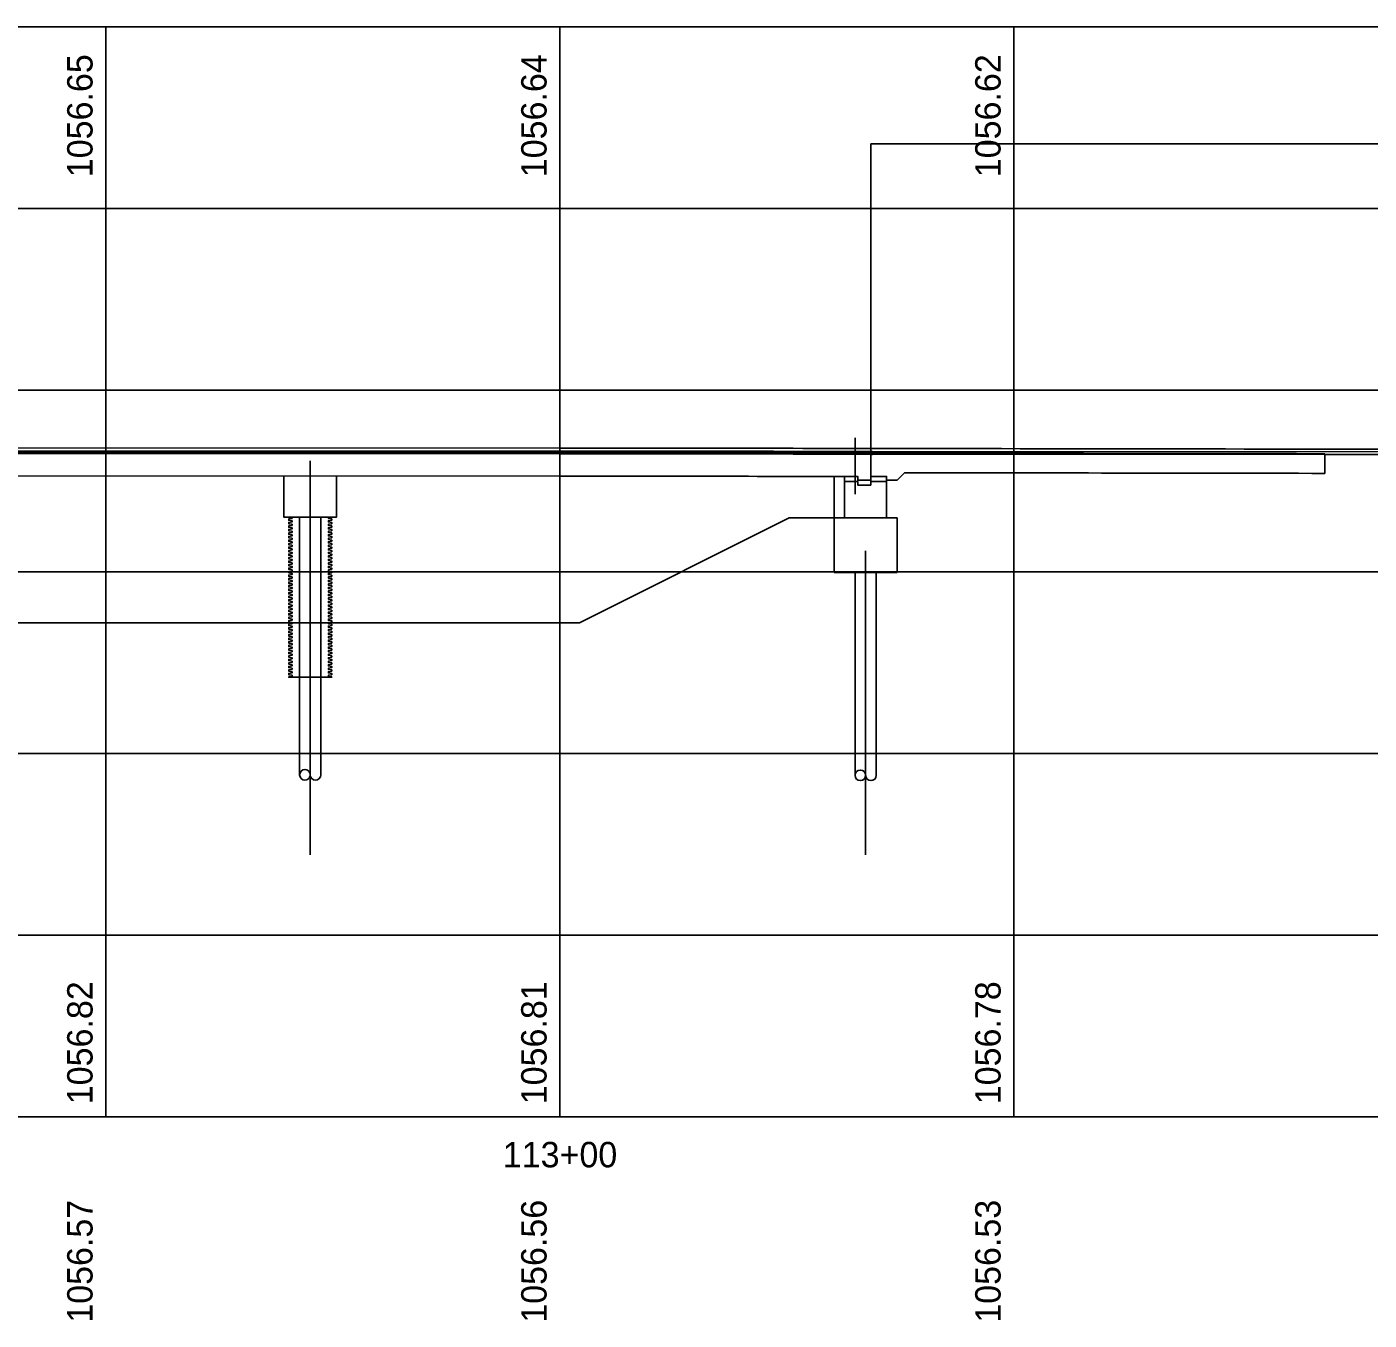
# Model space of a CAD drawing. Extents: x -2063 to 2068, y 79 to 1202.
# Drawn here: x -1598.7 to -1524.8, y 250.8 to 322 of the extents above; entities that cross this region are included whole.
import ezdxf

# ---------------------------------------------------------------- set-up
doc = ezdxf.new("R2010")
doc.units = 0
for name, color, linetype in [('BR_P_Gen_Approach_Slab', 7, 'Continuous'), ('BR_P_Gen_Joint_Filler', 7, 'Continuous'), ('BR_P_Slab_Object', 7, 'Continuous'), ('BR_X_Brg_Centerline', 7, 'Continuous'), ('BR_X_Gen_Approach_Slab', 7, 'Continuous'), ('BR_X_Slab_Object', 7, 'Continuous'), ('BR_X_Sub_Deep_Centerline', 7, 'Continuous'), ('BR_X_Sub_Deep_Object', 7, 'Continuous'), ('BR_X_Sub_Object', 7, 'Continuous'), ('PF_X_Ground_Line', 7, 'Continuous'), ('SC_Scratch1', 7, 'Continuous'), ('SC_Scratch2', 7, 'Continuous'), ('SC_Scratch3', 7, 'Continuous'), ('XS_P_Pavt_Surface', 7, 'Continuous')]:
    doc.layers.add(name, color=color, linetype=linetype)

msp = doc.modelspace()

# ---------------------------------------------------------------- linework, layer by layer
at = {"layer": 'BR_P_Gen_Approach_Slab'}
msp.add_line((-1552.207, 298.444), (-1527.207, 298.432), dxfattribs=at)
at = {"layer": 'BR_P_Gen_Joint_Filler'}
msp.add_lwpolyline([(-1552.207, 298.59), (-1552.123, 298.59), (-1552.123, 298.423), (-1552.207, 298.423)], close=True, dxfattribs=at)
at = {"layer": 'BR_P_Slab_Object'}
msp.add_line((-1552.207, 298.59), (-1552.207, 298.444), dxfattribs=at)
for points in [[(-1651.447, 298.617), (-1619.327, 298.63), (-1569.327, 298.61)], [(-1569.327, 298.464), (-1619.327, 298.484), (-1651.447, 298.471)]]:
    msp.add_lwpolyline(points, dxfattribs=at)
for centre in [(-1573.973, -11316.689), (-1573.973, -11316.835)]:
    msp.add_arc(centre, 11615.3, 89.8926323, 89.9770817, dxfattribs=at)
at = {"layer": 'BR_X_Brg_Centerline'}
for p, q in [((-1553.073, 299.349), (-1553.073, 296.245)), ((-1583.077, 298.081), (-1583.077, 276.394))]:
    msp.add_line(p, q, dxfattribs=at)
at = {"layer": 'BR_X_Gen_Approach_Slab'}
msp.add_line((-1527.207, 298.47), (-1527.207, 297.387), dxfattribs=at)
msp.add_lwpolyline([(-1550.352, 297.421), (-1550.763, 297.009), (-1551.341, 297.009)], dxfattribs=at)
for centre, end in [((-1631.827, -62201.629), 89.9270098), ((-1631.827, -62202.712), 89.92530917)]:
    msp.add_arc(centre, 62500.186, 89.90409154, end, dxfattribs=at)
at = {"layer": 'BR_X_Slab_Object'}
msp.add_line((-1552.207, 297.218), (-1552.207, 298.507), dxfattribs=at)
for points in [[(-1569.327, 298.526), (-1619.327, 298.546), (-1651.447, 298.533)], [(-1649.426, 297.243), (-1619.327, 297.255), (-1569.327, 297.235)]]:
    msp.add_lwpolyline(points, dxfattribs=at)
for centre, start in [((-1631.827, -62201.629), 89.9270098), ((-1631.827, -62202.92), 89.92886227)]:
    msp.add_arc(centre, 62500.186, start, 89.94270423, dxfattribs=at)
at = {"layer": 'BR_X_Sub_Deep_Centerline'}
msp.add_line((-1552.495, 293.128), (-1552.495, 276.394), dxfattribs=at)
at = {"layer": 'BR_X_Sub_Deep_Object'}
for p, q in [((-1583.66, 294.969), (-1583.66, 280.794)), ((-1582.493, 294.969), (-1582.493, 280.794)), ((-1553.075, 280.764), (-1553.075, 291.936)), ((-1551.909, 280.764), (-1551.909, 291.936))]:
    msp.add_line(p, q, dxfattribs=at)
msp.add_lwpolyline([(-1584.077, 294.969), (-1584.077, 294.907), (-1584.26, 294.876), (-1584.26, 294.808), (-1584.077, 294.776), (-1584.077, 294.714), (-1584.26, 294.683), (-1584.26, 294.614), (-1584.077, 294.583), (-1584.077, 294.523), (-1584.26, 294.492), (-1584.26, 294.423), (-1584.077, 294.392), (-1584.077, 294.33), (-1584.26, 294.298), (-1584.26, 294.23), (-1584.077, 294.199), (-1584.077, 294.136), (-1584.26, 294.105), (-1584.26, 294.037), (-1584.077, 294.006), (-1584.077, 293.943), (-1584.26, 293.912), (-1584.26, 293.844), (-1584.077, 293.812), (-1584.077, 293.75), (-1584.26, 293.718), (-1584.26, 293.65), (-1584.077, 293.619), (-1584.077, 293.556), (-1584.26, 293.525), (-1584.26, 293.457), (-1584.077, 293.426), (-1584.077, 293.363), (-1584.26, 293.332), (-1584.26, 293.264), (-1584.077, 293.232), (-1584.077, 293.17), (-1584.26, 293.139), (-1584.26, 293.07), (-1584.077, 293.039), (-1584.077, 292.977), (-1584.26, 292.945), (-1584.26, 292.877), (-1584.077, 292.846), (-1584.077, 292.783), (-1584.26, 292.752), (-1584.26, 292.684), (-1584.077, 292.652), (-1584.077, 292.59), (-1584.26, 292.559), (-1584.26, 292.49), (-1584.077, 292.459), (-1584.077, 292.397), (-1584.26, 292.365), (-1584.26, 292.297), (-1584.077, 292.266), (-1584.077, 292.203), (-1584.26, 292.172), (-1584.26, 292.104), (-1584.077, 292.073), (-1584.077, 292.01), (-1584.26, 291.979), (-1584.26, 291.911), (-1584.077, 291.879), (-1584.077, 291.817), (-1584.26, 291.785), (-1584.26, 291.717), (-1584.077, 291.686), (-1584.077, 291.623), (-1584.26, 291.592), (-1584.26, 291.524), (-1584.077, 291.493), (-1584.077, 291.43), (-1584.26, 291.399), (-1584.26, 291.331), (-1584.077, 291.299), (-1584.077, 291.237), (-1584.26, 291.206), (-1584.26, 291.137), (-1584.077, 291.106), (-1584.077, 291.044), (-1584.26, 291.012), (-1584.26, 290.944), (-1584.077, 290.913), (-1584.077, 290.85), (-1584.26, 290.819), (-1584.26, 290.751), (-1584.077, 290.719), (-1584.077, 290.657), (-1584.26, 290.626), (-1584.26, 290.557), (-1584.077, 290.526), (-1584.077, 290.464), (-1584.26, 290.432), (-1584.26, 290.364), (-1584.077, 290.333), (-1584.077, 290.27), (-1584.26, 290.239), (-1584.26, 290.171), (-1584.077, 290.14), (-1584.077, 290.077), (-1584.26, 290.046), (-1584.26, 289.978), (-1584.077, 289.946), (-1584.077, 289.884), (-1584.26, 289.852), (-1584.26, 289.784), (-1584.077, 289.753), (-1584.077, 289.69), (-1584.26, 289.659), (-1584.26, 289.591), (-1584.077, 289.56), (-1584.077, 289.497), (-1584.26, 289.466), (-1584.26, 289.398), (-1584.077, 289.366), (-1584.077, 289.304), (-1584.26, 289.273), (-1584.26, 289.204), (-1584.077, 289.173), (-1584.077, 289.111), (-1584.26, 289.079), (-1584.26, 289.011), (-1584.077, 288.98), (-1584.077, 288.917), (-1584.26, 288.886), (-1584.26, 288.818), (-1584.077, 288.786), (-1584.077, 288.724), (-1584.26, 288.693), (-1584.26, 288.624), (-1584.077, 288.593), (-1584.077, 288.531), (-1584.26, 288.499), (-1584.26, 288.431), (-1584.077, 288.4), (-1584.077, 288.337), (-1584.26, 288.306), (-1584.26, 288.238), (-1584.077, 288.207), (-1584.077, 288.144), (-1584.26, 288.113), (-1584.26, 288.045), (-1584.077, 288.013), (-1584.077, 287.951), (-1584.26, 287.92), (-1584.26, 287.851), (-1584.077, 287.82), (-1584.077, 287.757), (-1584.26, 287.726), (-1584.26, 287.658), (-1584.077, 287.627), (-1584.077, 287.564), (-1584.26, 287.533), (-1584.26, 287.465), (-1584.077, 287.433), (-1584.077, 287.371), (-1584.26, 287.34), (-1584.26, 287.271), (-1584.077, 287.24), (-1584.077, 287.178), (-1584.26, 287.146), (-1584.26, 287.078), (-1584.077, 287.047), (-1584.077, 286.984), (-1584.26, 286.953), (-1584.26, 286.885), (-1584.077, 286.853), (-1584.077, 286.791), (-1584.26, 286.76), (-1584.26, 286.691), (-1584.077, 286.66), (-1584.077, 286.598), (-1584.26, 286.566), (-1584.26, 286.498), (-1584.077, 286.467), (-1584.077, 286.404), (-1584.26, 286.373), (-1584.26, 286.305), (-1584.077, 286.274), (-1584.077, 286.211), (-1584.26, 286.18), (-1584.26, 286.166), (-1581.893, 286.166), (-1581.893, 286.18), (-1582.077, 286.211), (-1582.077, 286.274), (-1581.893, 286.305), (-1581.893, 286.373), (-1582.077, 286.404), (-1582.077, 286.467), (-1581.893, 286.498), (-1581.893, 286.566), (-1582.077, 286.598), (-1582.077, 286.66), (-1581.893, 286.691), (-1581.893, 286.76), (-1582.077, 286.791), (-1582.077, 286.853), (-1581.893, 286.885), (-1581.893, 286.953), (-1582.077, 286.984), (-1582.077, 287.047), (-1581.893, 287.078), (-1581.893, 287.146), (-1582.077, 287.178), (-1582.077, 287.24), (-1581.893, 287.271), (-1581.893, 287.34), (-1582.077, 287.371), (-1582.077, 287.433), (-1581.893, 287.465), (-1581.893, 287.533), (-1582.077, 287.564), (-1582.077, 287.627), (-1581.893, 287.658), (-1581.893, 287.726), (-1582.077, 287.757), (-1582.077, 287.82), (-1581.893, 287.851), (-1581.893, 287.92), (-1582.077, 287.951), (-1582.077, 288.013), (-1581.893, 288.045), (-1581.893, 288.113), (-1582.077, 288.144), (-1582.077, 288.207), (-1581.893, 288.238), (-1581.893, 288.306), (-1582.077, 288.337), (-1582.077, 288.4), (-1581.893, 288.431), (-1581.893, 288.499), (-1582.077, 288.531), (-1582.077, 288.593), (-1581.893, 288.624), (-1581.893, 288.693), (-1582.077, 288.724), (-1582.077, 288.786), (-1581.893, 288.818), (-1581.893, 288.886), (-1582.077, 288.917), (-1582.077, 288.98), (-1581.893, 289.011), (-1581.893, 289.079), (-1582.077, 289.111), (-1582.077, 289.173), (-1581.893, 289.204), (-1581.893, 289.273), (-1582.077, 289.304), (-1582.077, 289.366), (-1581.893, 289.398), (-1581.893, 289.466), (-1582.077, 289.497), (-1582.077, 289.56), (-1581.893, 289.591), (-1581.893, 289.659), (-1582.077, 289.69), (-1582.077, 289.753), (-1581.893, 289.784), (-1581.893, 289.852), (-1582.077, 289.884), (-1582.077, 289.946), (-1581.893, 289.978), (-1581.893, 290.046), (-1582.077, 290.077), (-1582.077, 290.14), (-1581.893, 290.171), (-1581.893, 290.239), (-1582.077, 290.27), (-1582.077, 290.333), (-1581.893, 290.364), (-1581.893, 290.432), (-1582.077, 290.464), (-1582.077, 290.526), (-1581.893, 290.557), (-1581.893, 290.626), (-1582.077, 290.657), (-1582.077, 290.719), (-1581.893, 290.751), (-1581.893, 290.819), (-1582.077, 290.85), (-1582.077, 290.913), (-1581.893, 290.944), (-1581.893, 291.012), (-1582.077, 291.044), (-1582.077, 291.106), (-1581.893, 291.137), (-1581.893, 291.206), (-1582.077, 291.237), (-1582.077, 291.299), (-1581.893, 291.331), (-1581.893, 291.399), (-1582.077, 291.43), (-1582.077, 291.493), (-1581.893, 291.524), (-1581.893, 291.592), (-1582.077, 291.623), (-1582.077, 291.686), (-1581.893, 291.717), (-1581.893, 291.785), (-1582.077, 291.817), (-1582.077, 291.879), (-1581.893, 291.911), (-1581.893, 291.979), (-1582.077, 292.01), (-1582.077, 292.073), (-1581.893, 292.104), (-1581.893, 292.172), (-1582.077, 292.203), (-1582.077, 292.266), (-1581.893, 292.297), (-1581.893, 292.365), (-1582.077, 292.397), (-1582.077, 292.459), (-1581.893, 292.49), (-1581.893, 292.559), (-1582.077, 292.59), (-1582.077, 292.652), (-1581.893, 292.684), (-1581.893, 292.752), (-1582.077, 292.783), (-1582.077, 292.846), (-1581.893, 292.877), (-1581.893, 292.945), (-1582.077, 292.977), (-1582.077, 293.039), (-1581.893, 293.07), (-1581.893, 293.139), (-1582.077, 293.17), (-1582.077, 293.232), (-1581.893, 293.264), (-1581.893, 293.332), (-1582.077, 293.363), (-1582.077, 293.426), (-1581.893, 293.457), (-1581.893, 293.525), (-1582.077, 293.556), (-1582.077, 293.619), (-1581.893, 293.65), (-1581.893, 293.718), (-1582.077, 293.75), (-1582.077, 293.812), (-1581.893, 293.844), (-1581.893, 293.912), (-1582.077, 293.943), (-1582.077, 294.006), (-1581.893, 294.037), (-1581.893, 294.105), (-1582.077, 294.136), (-1582.077, 294.199), (-1581.893, 294.23), (-1581.893, 294.298), (-1582.077, 294.33), (-1582.077, 294.392), (-1581.893, 294.423), (-1581.893, 294.492), (-1582.077, 294.523), (-1582.077, 294.583), (-1581.893, 294.614), (-1581.893, 294.683), (-1582.077, 294.714), (-1582.077, 294.776), (-1581.893, 294.808), (-1581.893, 294.876), (-1582.077, 294.907), (-1582.077, 294.969)], dxfattribs=at)
for centre, radius in [((-1583.368, 280.794), 0.292), ((-1552.785, 280.764), 0.29)]:
    msp.add_circle(centre, radius, dxfattribs=at)
for centre, radius in [((-1582.785, 280.794), 0.292), ((-1552.202, 280.764), 0.293)]:
    msp.add_arc(centre, radius, 180, 0, dxfattribs=at)
at = {"layer": 'BR_X_Sub_Object'}
for p, q in [((-1554.227, 291.936), (-1554.227, 294.936)), ((-1554.227, 294.936), (-1550.763, 294.936)), ((-1550.763, 294.936), (-1550.763, 291.936)), ((-1550.763, 291.966), (-1550.763, 291.936)), ((-1550.763, 291.936), (-1554.227, 291.936)), ((-1550.763, 291.936), (-1554.227, 291.936))]:
    msp.add_line(p, q, dxfattribs=at)
for points in [[(-1584.52, 297.241), (-1584.52, 294.969), (-1581.633, 294.969), (-1581.633, 297.24)], [(-1553.65, 297.218), (-1554.227, 297.218), (-1554.227, 294.936)], [(-1553.65, 294.936), (-1553.65, 297.218), (-1552.928, 297.218), (-1552.928, 297.009), (-1552.207, 297.009), (-1552.207, 297.218), (-1551.341, 297.218), (-1551.341, 294.936)]]:
    msp.add_lwpolyline(points, dxfattribs=at)
at = {"layer": 'PF_X_Ground_Line'}
for p, q in [((-1568.25, 289.166), (-1556.71, 294.936)), ((-1556.71, 294.936), (-1554.227, 294.936)), ((-1635.403, 289.166), (-1568.25, 289.166))]:
    msp.add_line(p, q, dxfattribs=at)
msp.add_lwpolyline([(-1669.327, 298.776), (-1619.327, 298.796), (-1569.327, 298.776)], dxfattribs=at)
for centre, radius, start, end in [((-1573.973, -11316.522), 11615.3, 89.8926323, 89.9770817), ((-1631.827, -62201.379), 62500.186, 89.89686769, 89.9270098)]:
    msp.add_arc(centre, radius, start, end, dxfattribs=at)
at = {"layer": 'SC_Scratch1'}
for p, q in [((-1969.327, 321.966), (-1244.327, 321.966)), ((-1594.327, 261.966), (-1594.327, 321.966)), ((-1569.327, 261.966), (-1569.327, 321.966)), ((-1544.327, 261.966), (-1544.327, 321.966)), ((-1969.327, 311.966), (-1244.327, 311.966)), ((-1969.327, 301.966), (-1244.327, 301.966)), ((-1969.327, 291.966), (-1244.327, 291.966)), ((-1969.327, 281.966), (-1244.327, 281.966)), ((-1969.327, 271.966), (-1244.327, 271.966)), ((-1969.327, 261.966), (-1244.327, 261.966))]:
    msp.add_line(p, q, dxfattribs=at)
msp.add_lwpolyline([(-1551.341, 296.946), (-1552.207, 296.946), (-1552.207, 296.738), (-1552.928, 296.738), (-1552.928, 296.946), (-1553.65, 296.946)], dxfattribs=at)
at = {"layer": 'SC_Scratch2'}
for p, q in [((-1594.327, 298.62), (-1594.327, 291.966)), ((-1569.327, 298.61), (-1569.327, 291.966)), ((-1544.327, 298.586), (-1544.327, 291.966))]:
    msp.add_line(p, q, dxfattribs=at)
at = {"layer": 'SC_Scratch3'}
for p, q in [((-1552.207, 296.738), (-1552.207, 315.53)), ((-1552.207, 315.53), (-1452.207, 315.53)), ((-1594.327, 298.786), (-1594.327, 291.966)), ((-1569.327, 298.776), (-1569.327, 291.966)), ((-1544.327, 298.746), (-1544.327, 291.966))]:
    msp.add_line(p, q, dxfattribs=at)
at = {"layer": 'XS_P_Pavt_Surface'}
for p, q in [((-1552.207, 298.59), (-1452.207, 298.542)), ((-1452.207, 298.396), (-1527.207, 298.432))]:
    msp.add_line(p, q, dxfattribs=at)

# ---------------------------------------------------------------- texts
at = {"layer": 'SC_Scratch1'}
for s, p in [('1056.65', (-1595.06, 313.69)), ('1056.64', (-1570.06, 313.69)), ('1056.62', (-1545.06, 313.69)), ('1056.82', (-1595.06, 262.658)), ('1056.81', (-1570.06, 262.658)), ('1056.78', (-1545.06, 262.658)), ('1056.57', (-1595.06, 250.63)), ('1056.56', (-1570.06, 250.63)), ('1056.53', (-1545.06, 250.63))]:
    msp.add_text(s, height=1.4, rotation=90, dxfattribs=at).set_placement(p)
msp.add_text('113+00', height=1.4, dxfattribs=at).set_placement((-1572.469, 259.185))

doc.saveas('drawing.dxf')
